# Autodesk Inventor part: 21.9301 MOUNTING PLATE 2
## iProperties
Created: 2011-01
Part Number: 21.9301 MOUNTING PLATE 2
Document SubType Name: Modeling
Designer: Administrator
Density: 7.85 g/cm^3
Material: Steel
Mass: 190.743 g
Surface Area: 117.899 cm^2
Volume: 24.2984 cm^3
Author: Administrator
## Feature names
1. Revolution1
2. Shell1
3. Extrusion2
4. Extrusion3
5. Extrusion4
